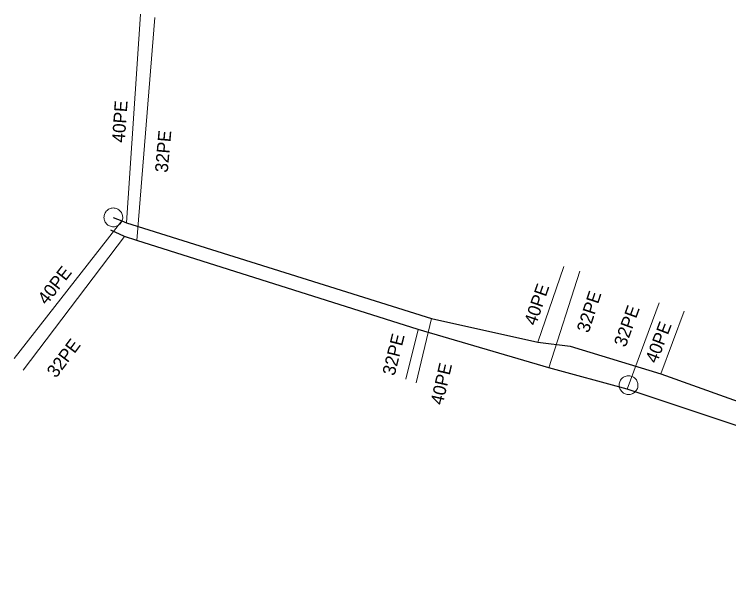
# Model space of a CAD drawing. Extents: x -741806 to -738704, y -1059275 to -1055387.
# Drawn here: x -740355.77 to -740322.44, y -1057219.16 to -1057192.37 of the extents above; entities that cross this region are included whole.
import ezdxf

# ---------------------------------------------------------------- set-up
doc = ezdxf.new("R2010")
doc.units = 0
doc.header["$LTSCALE"] = 0.4
for name, color, linetype, lineweight in [('2', 7, 'Continuous', 25), ('21', 7, 'Continuous', 13), ('3', 7, 'Continuous', 13), ('51', 7, 'Continuous', 13), ('52', 7, 'Continuous', 25), ('56', 7, 'Continuous', 13)]:
    doc.layers.add(name, color=color, linetype=linetype, lineweight=lineweight)
doc.layers.add('54', color=7, linetype='Continuous')
doc.layers.add('55', color=7, linetype='Continuous')

msp = doc.modelspace()

# ---------------------------------------------------------------- linework, layer by layer
at = {"layer": '2'}
msp.add_lwpolyline([(-740351.149, -1057201.84), (-740350.76, -1057202.01), (-740350.539, -1057202.1), (-740336.309, -1057206.55), (-740331.34, -1057207.659), (-740329.829, -1057207.85), (-740325.609, -1057209.139), (-740314.399, -1057213.149), (-740304.43, -1057216.419), (-740302.66, -1057217.22), (-740301.579, -1057218.07)], dxfattribs=at)
at = {"layer": '21'}
for p, q in [((-740350.059, -1057202.919), (-740349.21, -1057192.52)), ((-740350.629, -1057202.74), (-740355.36, -1057208.96)), ((-740330.829, -1057208.86), (-740329.379, -1057204.35)), ((-740327.18, -1057209.85), (-740325.68, -1057205.83)), ((-740336.92, -1057207.07), (-740337.5, -1057209.379))]:
    msp.add_line(p, q, dxfattribs=at)
at = {"layer": '3'}
msp.add_lwpolyline([(-740350.747, -1057202.015), (-740350.732, -1057201.973), (-740350.72, -1057201.928), (-740350.713, -1057201.882), (-740350.711, -1057201.838), (-740350.714, -1057201.792), (-740350.721, -1057201.746), (-740350.734, -1057201.702), (-740350.75, -1057201.659), (-740350.772, -1057201.619), (-740350.797, -1057201.581), (-740350.826, -1057201.545), (-740350.859, -1057201.513), (-740350.895, -1057201.485), (-740350.933, -1057201.46), (-740350.974, -1057201.439), (-740351.017, -1057201.423), (-740351.061, -1057201.412), (-740351.106, -1057201.405), (-740351.152, -1057201.403), (-740351.198, -1057201.406), (-740351.243, -1057201.414), (-740351.287, -1057201.425), (-740351.33, -1057201.442), (-740351.371, -1057201.463), (-740351.409, -1057201.489), (-740351.444, -1057201.518), (-740351.476, -1057201.55), (-740351.505, -1057201.586), (-740351.529, -1057201.625), (-740351.55, -1057201.666), (-740351.566, -1057201.708), (-740351.577, -1057201.752), (-740351.584, -1057201.798), (-740351.586, -1057201.845), (-740351.584, -1057201.889), (-740351.576, -1057201.935), (-740351.564, -1057201.979), (-740351.547, -1057202.022), (-740351.526, -1057202.062), (-740351.501, -1057202.1), (-740351.472, -1057202.136), (-740351.439, -1057202.168), (-740351.404, -1057202.197), (-740351.365, -1057202.221), (-740351.324, -1057202.241), (-740351.281, -1057202.258), (-740351.237, -1057202.27), (-740351.192, -1057202.276), (-740351.145, -1057202.278), (-740351.099, -1057202.275), (-740351.055, -1057202.267), (-740351.01, -1057202.256), (-740350.968, -1057202.238), (-740350.927, -1057202.218), (-740350.889, -1057202.192), (-740350.853, -1057202.163), (-740350.822, -1057202.131), (-740350.793, -1057202.094), (-740350.768, -1057202.056), (-740350.748, -1057202.016)], dxfattribs=at)
at = {"layer": '51'}
msp.add_lwpolyline([(-740326.957, -1057209.256), (-740327, -1057209.242), (-740327.045, -1057209.233), (-740327.091, -1057209.229), (-740327.136, -1057209.229), (-740327.182, -1057209.234), (-740327.227, -1057209.244), (-740327.27, -1057209.259), (-740327.312, -1057209.278), (-740327.351, -1057209.301), (-740327.388, -1057209.328), (-740327.422, -1057209.359), (-740327.453, -1057209.394), (-740327.479, -1057209.431), (-740327.502, -1057209.471), (-740327.519, -1057209.513), (-740327.534, -1057209.557), (-740327.543, -1057209.601), (-740327.547, -1057209.647), (-740327.546, -1057209.693), (-740327.541, -1057209.739), (-740327.531, -1057209.783), (-740327.517, -1057209.827), (-740327.497, -1057209.868), (-740327.475, -1057209.907), (-740327.447, -1057209.945), (-740327.416, -1057209.979), (-740327.382, -1057210.008), (-740327.344, -1057210.035), (-740327.304, -1057210.057), (-740327.262, -1057210.076), (-740327.219, -1057210.089), (-740327.174, -1057210.098), (-740327.128, -1057210.103), (-740327.083, -1057210.103), (-740327.037, -1057210.097), (-740326.992, -1057210.088), (-740326.949, -1057210.073), (-740326.907, -1057210.054), (-740326.868, -1057210.03), (-740326.832, -1057210.003), (-740326.797, -1057209.972), (-740326.767, -1057209.938), (-740326.741, -1057209.901), (-740326.718, -1057209.861), (-740326.7, -1057209.819), (-740326.685, -1057209.775), (-740326.677, -1057209.73), (-740326.672, -1057209.685), (-740326.673, -1057209.639), (-740326.678, -1057209.593), (-740326.689, -1057209.549), (-740326.702, -1057209.505), (-740326.722, -1057209.464), (-740326.745, -1057209.424), (-740326.772, -1057209.387), (-740326.803, -1057209.353), (-740326.837, -1057209.323), (-740326.875, -1057209.296), (-740326.915, -1057209.274), (-740326.956, -1057209.257)], dxfattribs=at)
at = {"layer": '52'}
msp.add_lwpolyline([(-740301.14, -1057219.159), (-740301.32, -1057219.01), (-740301.539, -1057218.81), (-740303.28, -1057217.99), (-740314.489, -1057214.08), (-740327.18, -1057209.85), (-740330.829, -1057208.86), (-740336.92, -1057207.07), (-740350.059, -1057202.919), (-740350.629, -1057202.74), (-740351.27, -1057202.44)], dxfattribs=at)
at = {"layer": '56'}
for p, q in [((-740349.879, -1057192.37), (-740350.539, -1057202.1)), ((-740355.77, -1057208.429), (-740350.76, -1057202.01)), ((-740330.129, -1057204.129), (-740331.34, -1057207.659)), ((-740324.51, -1057206.22), (-740325.609, -1057209.139)), ((-740337.02, -1057209.55), (-740336.309, -1057206.55))]:
    msp.add_line(p, q, dxfattribs=at)

# ---------------------------------------------------------------- texts
at = {"layer": '54'}
for rotation, p in [(85, (-740348.612, -1057199.768)), (72, (-740328.975, -1057207.264)), (70, (-740327.25, -1057207.928)), (76, (-740338.026, -1057209.256)), (53, (-740353.824, -1057209.364))]:
    msp.add_text('32PE', height=0.6, rotation=rotation, dxfattribs=at).set_placement(p)
at = {"layer": '55'}
for rotation, p in [(86, (-740350.617, -1057198.37)), (52, (-740354.263, -1057205.962)), (71, (-740331.436, -1057206.922)), (69, (-740325.792, -1057208.685)), (77, (-740335.78, -1057210.622))]:
    msp.add_text('40PE', height=0.6, rotation=rotation, dxfattribs=at).set_placement(p)

doc.saveas('drawing.dxf')
